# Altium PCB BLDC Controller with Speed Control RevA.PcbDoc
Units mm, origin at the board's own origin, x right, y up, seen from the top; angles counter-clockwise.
Board outline 60 x 60 mm, 2 copper layers (Top Layer, Bottom Layer), stack 1.575 mm thick; 48 components, 34 nets, 169 pads, 129 vias.
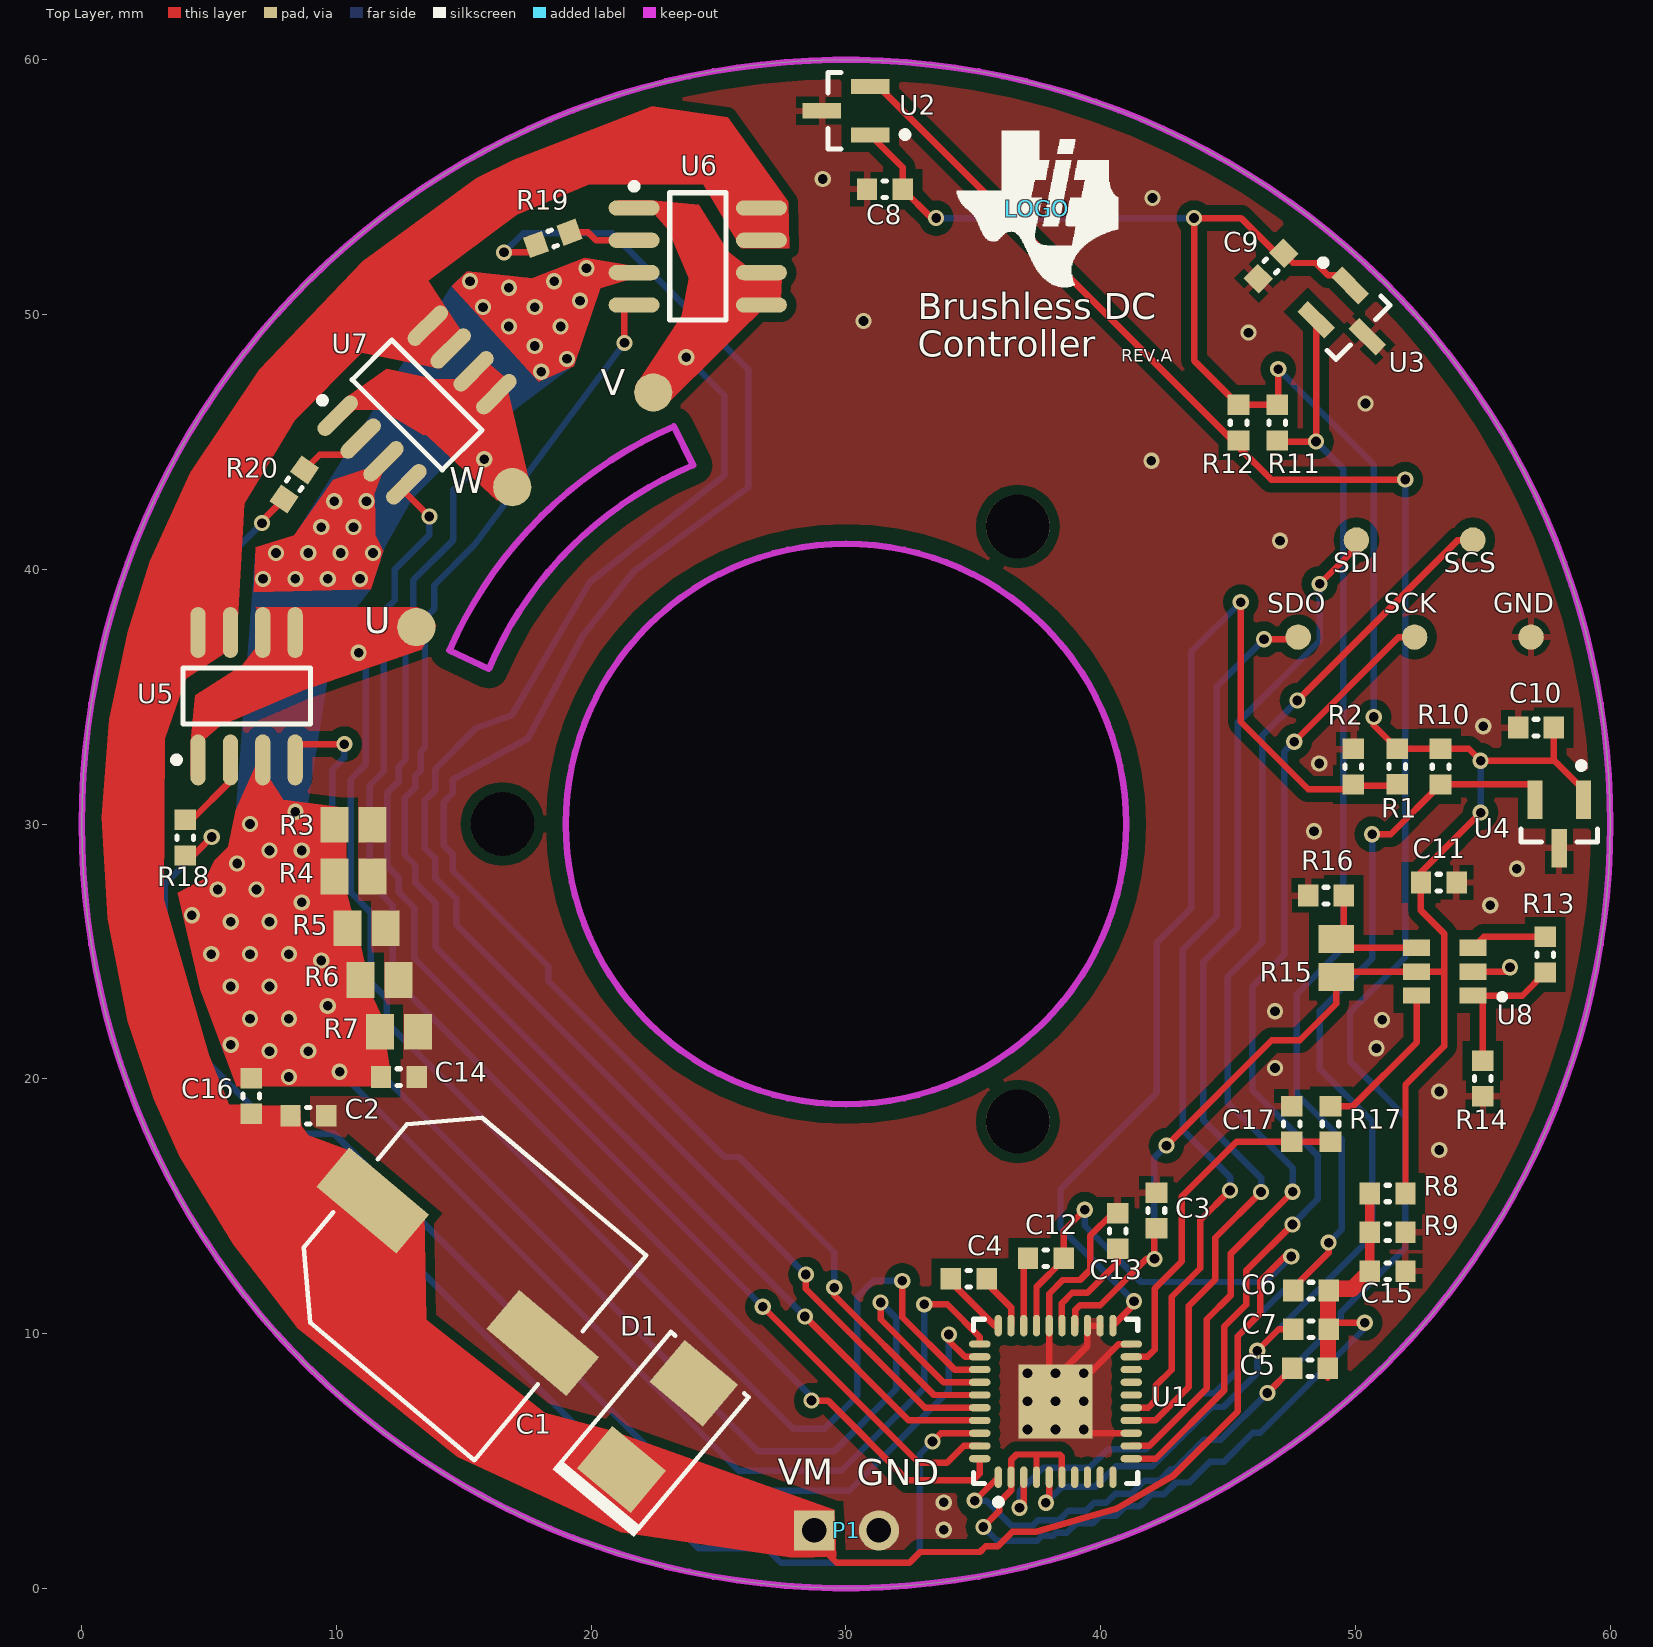
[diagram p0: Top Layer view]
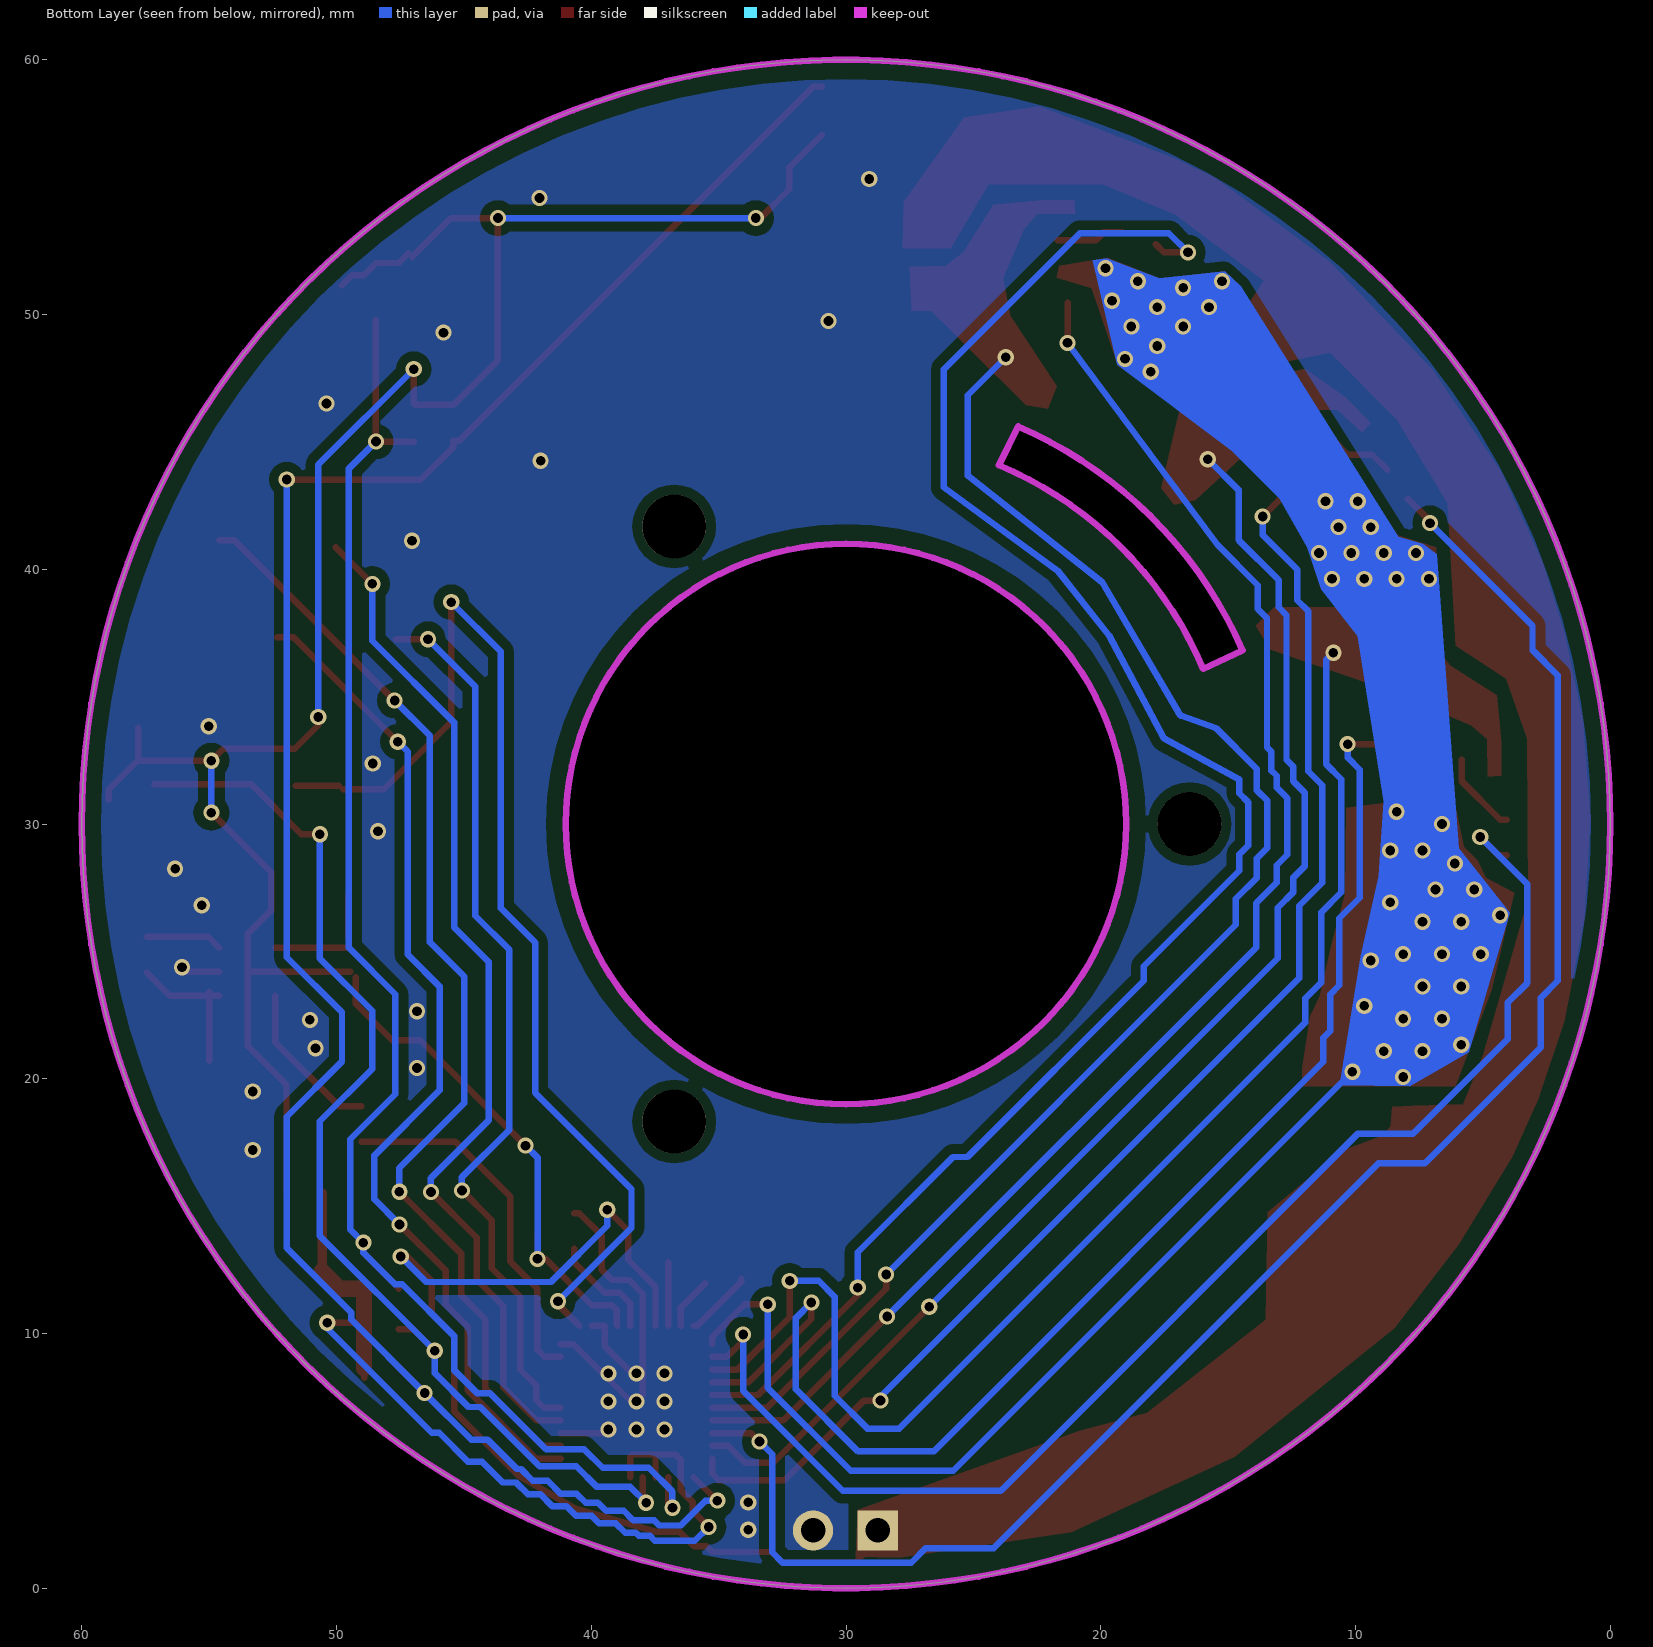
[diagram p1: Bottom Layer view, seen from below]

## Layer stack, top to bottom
Top Layer: signal copper 0.0356
Dielectric: core 1.5037, FR-4, Dk 4.8
Bottom Layer: signal copper 0.0356

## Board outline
30,0 cw(c30,30) 0,30 cw(c30,30) 30,60 cw(c30,30) 60,30 cw(c30,30)
cut-out: 30,19 cw(c30,30) 19,30 cw(c30,30) 30,41 cw(c30,30) 41,30 cw(c30,30)
cut-out: 15.976,36.086 14.431,36.816 cw(c30.032,29.993) 23.246,45.61 23.996,44.084 ccw(c29.827,30.217)

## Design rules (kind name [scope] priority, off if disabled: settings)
AcuteAngle [All] p1: minimum=1.50000000000000E+0001 checktracksonly=FALSE
AssemblyTestPointUsage [All] p1: valid=2
Clearance Clearance_BoardEdge_MountingHoles [OnCopper and InComponentClass('Mounting Holes') vs IsKeepOut] p1: gap=1.016
Clearance Clearance_BoardEdge_Poly [OnCopper and InPoly vs IsKeepOut] p2: gap=0.635
Clearance Clearance_BoardEdge [OnCopper and Not InComponentClass('Logo') and not InComponentClass('FiducialMark') and not InRegion(1000,500,4000,800) and Not IsKeepout and NOT IsRegion and NOT IsVia vs IsKeepOut] p3: gap=0.559
Clearance Clearance_Poly [InPolygon] p4: gap=0.381
Clearance [All] p5: gap=0.203
ComponentClearance ComponentClearance_Logo [InComponentClass('Logo')] p1: gap=1.27 collisioncheckmode=3 verticalgap=0.254 showdistances=FALSE
ComponentClearance ComponentClearance_ScrewToNut [(HasFootprint('NY PMS 440 0025 PH')) vs (HasFootprint('Keystone_1902C'))] p2: gap=0.127 collisioncheckmode=3 verticalgap=0.254 showdistances=FALSE
ComponentClearance ComponentClearance_MountingHoles [InComponentClass('Mounting Holes')] p3: gap=6.35 collisioncheckmode=3 verticalgap=2540 showdistances=FALSE
ComponentClearance ComponentClearance_SmallPassives [HasFootprint('0201*') or HasFootprint('0402*') or HasFootprint('0508') or HasFootprint('0603*') or HasFootprint('0612') or HasFootprint('0805*') or HasFootprint('0815*') or HasFootprint('0830*') or HasFootprint('1206*') or HasFootprint('1210*') or HasFootprint('1808*') or HasFootprint('1812*') or HasFootprint('1825*') or HasFootprint('2010*') or HasFootprint('2220*') or HasFootprint('2225*') or HasFootprint('2512*') or HasFootprint('2728*') or HasFootprint('3518*') vs HasFootprint('0201*') or HasFootprint('0402*') or HasFootprint('0508') or HasFootprint('0603*') or HasFootprint('0612') or HasFootprint('0805*') or HasFootprint('0815*') or HasFootprint('0830*') or HasFootprint('1206*') or HasFootprint('1210*') or HasFootprint('1808*') or HasFootprint('1812*') or HasFootprint('1825*') or HasFootprint('2010*') or HasFootprint('2220*') or HasFootprint('2225*') or HasFootprint('2512*') or HasFootprint('2728*') or HasFootprint('3518*')] p4: gap=0.508 collisioncheckmode=3 verticalgap=0.254 showdistances=FALSE
ComponentClearance ComponentClearance_THtoSMT [IsThruComponent vs IsSMTComponent] p5: gap=1.38 collisioncheckmode=3 verticalgap=0.762 showdistances=FALSE
ComponentClearance ComponentClearance_THtoTH [IsThruComponent vs IsThruComponent] p6: gap=0 collisioncheckmode=3 verticalgap=0.762 showdistances=FALSE
ComponentClearance [All] p7: gap=1.016 collisioncheckmode=3 verticalgap=0.254 showdistances=FALSE
DiffPairsRouting [All] p1: maxlimit=2.54 minlimit=0.254 mostfreqgap=0.254 maxuncoupledlength=25.4
FabricationTestPointUsage TestPointUsage [All] p1: valid=2 allowmultiple=FALSE
FabricationTestpoint Testpoint [All] p1: side=3 testpointundercomponent=TRUE minsize=1.016 maxsize=2.54 preferedsize=1.524 minholesize=0 maxholesize=1.016 preferedholesize=0.813 testpointgrid=0.025 allowsidetop=TRUE allowsidebottom=TRUE usegrid=TRUE gridtolerance=0
FanoutControl Fanout_LCC [IsLCC] p1: bgadir=Out bgaviamode=Centered fanoutstyle=Auto fanoutdirection=Alternating viagrid=0.025 // Fanout_LCC (Default Rule)
FanoutControl Fanout_BGA [IsBGA] p2: bgadir=Out bgaviamode=Centered fanoutstyle=Auto fanoutdirection=Alternating viagrid=0.025 // Fanout_BGA (Default Rule)
FanoutControl Fanout_Default [All] p4: bgadir=Out bgaviamode=Centered fanoutstyle=Auto fanoutdirection=Alternating viagrid=0.025 // Fanout_Default (Default Rule)
FanoutControl Fanout_Small [(CompPinCount < 5)] p5: bgadir=Out bgaviamode=Centered fanoutstyle=Auto fanoutdirection=OutThenIn viagrid=0.025 // Fanout_Small (Default Rule)
HoleSize [All] p1: absolutevalues=TRUE maxlimit=6.375 minlimit=0.203 maxpercent=80.000 minpercent=20.000
MinimumAnnularRing [All] p1: minimumring=0.127
MinimumSolderMaskSliver MinimumSolderMaskSliver_Logo [InComponentClass('Logo') vs InComponentClass('Logo')] p1: minsoldermaskwidth=0.018
MinimumSolderMaskSliver [All] p2: minsoldermaskwidth=0.076
PlaneConnect [All] p1: planeconnectstyle=Relief reliefexpansion=0.254 reliefentries=4 reliefconductorwidth=0.254 reliefairgap=0.254
PolygonConnect PolygonConnect_1 [IsNamedPolygon('Top GND plane') or IsNamedPolygon('Bottom GND plane') vs not ( InComponent('U1') or InComponent('C1') or InComponent('C2') or InComponent('D1') or InComponent('P1') or InComponent('P2') or InComponent('R3') or InComponent('R4') or InComponent('R5') or InComponent('R6') or InComponent('R7') or InComponent('C14') or IsStitchingVia or IsVia)] p1: connectstyle=Relief reliefconductorwidth=0.254 reliefentries=4 polygonreliefangle="90 Angle" airgapwidth=0.254
PolygonConnect [All] p2: connectstyle=Direct reliefconductorwidth=0.254 reliefentries=4 polygonreliefangle="90 Angle" airgapwidth=0.254
RoutingVias [All] p1: holewidth=0.406 width=0.864 viastyle="Through Hole" minholewidth=0.203 minwidth=0.635 maxholewidth=1.016 maxwidth=1.651
SMDToCorner [All] p1: distance=0
SilkToSilkClearance [All] p1: silktosilkclearance=0.076
SilkscreenOverComponentPads [All] p1: minsilkscreentomaskgap=0.051
SolderMaskExpansion [All] p1: expansion=0.076
Width [All] p1: maxlimit=2.54 minlimit=0.152 preferedwidth=0.254 checkconnectedcopper=TRUE
14 further rules are at their usual default settings.

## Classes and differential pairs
component class Logo: LOGO

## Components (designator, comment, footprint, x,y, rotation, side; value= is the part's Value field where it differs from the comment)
C1 "PartNumber" SM_RADIAL_G 14.757,12.417 r320 top
C2 "PartNumber" 0603L 8.89,18.542 r0 top
C3 "PartNumber" 0603L 42.189,14.826 r90 top
C4 "PartNumber" 0603L 34.819,12.153 r0 top
C5 "PartNumber" 0603L 48.218,8.636 r0 top
C6 "PartNumber" 0603L 48.26,11.684 r0 top
C7 "PartNumber" 0603L 48.26,10.16 r0 top
C8 "PartNumber" 0603L 31.523,54.925 r180 top
C9 "PartNumber" 0603L 46.686,51.91 r225 top
C10 "PartNumber" 0603L 57.087,33.787 r180 top
C11 "PartNumber" 0603L 53.274,27.702 r0 top
C12 "PartNumber" 0603L 37.846,12.954 r0 top
C13 "PartNumber" 0603L 40.667,14.02 r90 top
C14 "PartNumber" 0603L 12.446,20.066 r0 top
C15 "PartNumber" 0603L 51.266,12.446 r0 top
C16 "PartNumber" 0603L 6.647,19.32 r90 top
C17 "PartNumber" 0603L 47.498,18.226 r90 top
D1 "PartNumber" SMB 22.606,6.35 r50 top
LOGO "Texas Instruments" TI_Symbol_Overlay_Medium 37.517,54.159 r0 top
P1 "JUMPER_2X100MIL" "2PIN HEADER" 27.601,1.045 r0 top
R1 "PartNumber" 0603L 51.642,32.254 r90 top
R2 "PartNumber" 0603L 49.917,32.253 r270 top
R3 "PartNumber" 0805L 10.668,29.972 r180 top
R4 "PartNumber" 0805L 10.668,27.94 r180 top
R5 "PartNumber" 0805L 11.176,25.908 r180 top
R6 "PartNumber" 0805L 11.684,23.876 r180 top
R7 "PartNumber" 0805L 12.446,21.844 r180 top
R8 "PartNumber" 0603L 51.266,15.494 r0 top
R9 "PartNumber" 0603L 51.266,13.97 r180 top
R10 "PartNumber" 0603L 53.342,32.253 r90 top
R11 "PartNumber" 0603L 46.936,45.754 r90 top
R12 "PartNumber" 0603L 45.412,45.754 r90 top
R13 "PartNumber" 0603L 57.457,24.87 r90 top
R14 "PartNumber" 0603L 55.003,20.007 r90 top
R15 "PartNumber" 0805L 49.247,24.742 r270 top
R16 "PartNumber" 0603L 48.847,27.192 r0 top
R17 "PartNumber" 0603L 49.022,18.226 r90 top
R18 "PartNumber" 0603L 4.064,29.464 r90 top
R19 "PartNumber" 0603L 18.488,52.991 r20 top
R20 "PartNumber" 0603L 8.341,43.333 r55 top
U1 "DRV8308" RHA0040A 38.229,7.332 r90 top
U2 "DRV5013" DBZ0003A_N 30,58 r180 top
U3 "DRV5013" DBZ0003A_N 49.799,49.799 r315 top
U4 "DRV5013" DBZ0003A_N 58,30 r270 top
U5 "CSD88537ND" SO-8_N 6.469,35.018 r90 top
U6 "CSD88537ND" SO-8_N 24.181,52.281 r0 top
U7 "CSD88537ND" SO-8_N 13.16,46.452 r45 top
U8 "LTC6992IS6-2" SOT23-6 53.47,24.202 r180 top

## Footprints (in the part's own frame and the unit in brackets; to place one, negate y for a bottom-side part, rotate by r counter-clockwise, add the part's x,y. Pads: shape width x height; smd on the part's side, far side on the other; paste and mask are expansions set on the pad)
"2PIN HEADER" [mil]
  rect 62x62 hole 38: 1(45.32,48.03)
  round 62 hole 38: 2(145.32,48.03)
0603L [mm] "0603 from SM-752 data"
  rect 0.8x0.85 smd: 1(-0.7,0) 2(0.7,0)
  silkscreen extent -0.07,-0.33 0.07,0.33, body extent -0.87,-0.47 0.87,0.47, height 0.85
0805L [mm] "0805 from SM-752 data"
  rect 1.1x1.4 smd: 1(-0.75,0) 2(0.75,0)
  body extent -1.1,-0.72 1.1,0.72, height 1.1
DBZ0003A_N [mm] "SOT23, 3-Leads, Body 2.9x1.3mm, Pitch 0.95mm, Lead Span 2.4mm, IPC Medium Density"
  rect 1.5x0.6 smd: 1(-0.95,0.95) 2(-0.95,-0.95) 3(0.95,0)
  silkscreen extent -2.44,-1.5 0.7,1.5, body extent -0.7,-1.52 0.7,1.52, height 1.12
RHA0040A [mm] "QFN, 40-Leads, Body 6x6mm, Pitch 0.5mm, Thermal Pad 2.9x2.9mm, TI Recommended"
  oval 0.85x0.28 smd paste-0.025 mask+0.07: 1(-2.975,2.25) 2(-2.975,1.75) 3(-2.975,1.25) 4(-2.975,0.75) 5(-2.975,0.25) 6(-2.975,-0.25) 7(-2.975,-0.75) 8(-2.975,-1.25) 9(-2.975,-1.75) 10(-2.975,-2.25) 21(2.975,-2.25) 22(2.975,-1.75) 23(2.975,-1.25) 24(2.975,-0.75) 25(2.975,-0.25) 26(2.975,0.25) 27(2.975,0.75) 28(2.975,1.25) 29(2.975,1.75) 30(2.975,2.25)
  oval 0.28x0.85 smd paste-0.025 mask+0.07: 11(-2.25,-2.975) 12(-1.75,-2.975) 13(-1.25,-2.975) 14(-0.75,-2.975) 15(-0.25,-2.975) 16(0.25,-2.975) 17(0.75,-2.975) 18(1.25,-2.975) 19(1.75,-2.975) 20(2.25,-2.975) 31(2.25,2.975) 32(1.75,2.975) 33(1.25,2.975) 34(0.75,2.975) 35(0.25,2.975) 36(-0.25,2.975) 37(-0.75,2.975) 38(-1.25,2.975) 39(-1.75,2.975) 40(-2.25,2.975)
  rect 2.9x2.9 smd paste-2.45 mask+0.07: 41(0,0)
  silkscreen extent -4.08,-3.22 3.22,3.22, body extent -3.08,-3.08 3.08,3.08, height 1
SM_RADIAL_G [mm] "10 x 10.2mm:  Panasonic G"
  rect 4.1x2 smd: 1(-4.35,0) 2(4.35,0)
  silkscreen extent -5.25,-5.25 5.25,5.25, body extent -5.26,-5.26 5.26,5.26, height 10.5
SMB [mm] "Molded Diode, 2-Leads, Body 5.4x3.6mm, IPC Medium Density, based on OnSemi component dimensions"
  rect 2.159x2.743 smd: 1(-2.21,0) 2(2.21,0)
  silkscreen extent -3.94,-2.08 3.18,2.08, body extent -2.7,-1.8 2.7,1.8, height 2.32
SO-8_N [mm] "SOIC, 8-Leads, Body 4.9x3.9mm, Pitch 1.27mm, IPC Medium Density"
  oval 2x0.6 smd: 1(-2.5,1.905) 2(-2.5,0.635) 3(-2.5,-0.635) 4(-2.5,-1.905) 5(2.5,-1.905) 6(2.5,-0.635) 7(2.5,0.635) 8(2.5,1.905)
  silkscreen extent -2.62,-2.5 1.1,2.88, body extent -2,-2.5 2,2.5, height 1.75
SOT23-6 [mil]
  rect 42x25 smd: 1(-45,37) 2(-45,0) 3(-45,-37) 4(42,-37) 5(42,0) 6(42,37)
TI_Symbol_Overlay_Medium [mm]
  silkscreen extent -3.16,-3.09 3.16,3.06

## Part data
C1: library part EEE-FC1H101P
C2 C3 C4 C5 C6 C7 C8 C9 C10 C11 C12 C13 C14 C15 C16 C17: library part 0603YC104JAT2A
D1: library part 10BQ030TRPBF
LOGO: library part TI_Logo, "Texas Instrument Corporate Signature"
P1: "Header, Male 2-pin, 100mil spacing,"
R1 R2 R8 R9 R10 R11 R12 R13 R14 R16 R17 R18 R19 R20: library part CRCW06031K00FKEA
R3 R4 R5 R6 R7: library part CRCW08051K13FKEA
R15: library part CRCW08051K00FKEA
U2 U3 U4: library part DRV5xxxDBZ, "Hall sensor"
U5 U6 U7: library part FDS8949, "MOSFET N-CH DUAL 30V 3.5A SOP8"
U8: library part LTC6992-2

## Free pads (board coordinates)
  round 1.5 smd: 0(13.131,37.73) 0(16.895,43.225) 0(22.431,46.944)
  round 2.5 hole 2.5 unplated: 0(16.513,30) 0(36.744,18.32) 0(36.744,41.68)
  round 1 smd: 0(47.752,37.338) 0(50.038,41.148) 0(52.324,37.338) 0(54.61,41.148) 0(56.896,37.338)

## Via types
v1: diameter 0.635, hole 0.381, Top Layer to Bottom Layer, tented both sides, 120 vias
v2: diameter 0.635, hole 0.381, Top Layer to Bottom Layer, 9 vias

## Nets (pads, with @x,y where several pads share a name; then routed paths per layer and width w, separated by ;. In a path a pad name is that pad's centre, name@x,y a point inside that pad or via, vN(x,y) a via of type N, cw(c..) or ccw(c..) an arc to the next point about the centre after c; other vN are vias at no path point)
2.5V: C5.2 C6.2 C7.2 C15.1 R8.1 R9.2 U1.2 U1.4 U1.6 | length 35.6
  Top Layer w0.254: v1(35.392,2.404) 36.026,3.037 36.026,3.382 36.479,3.835 U1.2 36.479,5.032 36.693,5.246 37.414,5.246 ; U1.4 37.479,5.182 ; 37.479,5.246 38.393,5.246 38.479,5.161 U1.6 ; C7.2@48.917,10.418 v1(50.367,10.418) ; C5.2@48.918,8.261 C5.2
  Top Layer w0.381: C15.1 R8.1
  Top Layer w0.635: C6.2@48.909,11.755 49.875,11.755 C15.1 ; C5.2 C6.2@48.918,11.746
  Bottom Layer w0.254: v1(35.392,2.404) 35.938,1.857 37.504,1.857 37.71,2.063 38.133,2.063 38.246,2.175 38.671,2.175 39.034,2.539 39.689,2.539 39.985,2.835 40.589,2.835 40.979,3.224 41.539,3.224 42.007,3.692 42.499,3.692 42.954,4.147 43.473,4.147 44.289,4.963 44.841,4.963 45.974,6.096 46.262,6.096 50.367,10.201 v1(50.367,10.418)
CLK: R17.2 U8.6 | length 6.3
  Top Layer w0.254: R17.2 49.905,18.926 52.403,21.424 U8.6
CLKIN: C17.1 R17.1 U1.19 | length 14.2
  Top Layer w0.254: U1.19 41.838,9.082 42.115,9.359 42.115,11.759 43.182,12.826 43.182,15.375 45.332,17.526 C17.1 R17.1
CP1: C4.1 U1.30 | length 2.7
  Top Layer w0.254: C4.1 34.119,12.019 35.831,10.307 U1.30
CP2: C4.2 U1.29 | length 2.1
  Top Layer w0.254: C4.2@35.519,11.979 36.479,11.019 U1.29
DIR: R1.1 R2.2 U1.21 | length 44.6
  Top Layer w0.254: U1.21 41.305,11.133 v1(41.305,11.261) ; v1(45.496,38.711) 45.496,34.014 48.143,31.367 R2.2@49.732,31.367 ; R2.2@49.917,31.509 R1.1@51.596,31.509
  Bottom Layer w0.254: v1(41.305,11.261) 38.421,14.144 38.421,15.662 42.201,19.442 42.201,25.344 43.548,26.692 43.548,36.764 v1(45.496,38.711)
DIV: R15.1 R16.2 U8.4 | length 4.5
  Top Layer w0.254: R15.1@49.538,25.142 U8.4 ; R15.1@49.547,25.572 R16.2
GND: C1.2 C2.2 C3.2 C8.2 C9.2 C10.2 C11.2 C13.2 C14.2 C15.2 C17.2 D1.2 P1.2 pad.0@56.896,37.338 R2.1 R3.1 R4.1 R5.1 R6.1 R7.1 R9.1 R14.1 R16.1 U1.13 U1.20 U1.22 U1.23 U1.26 U1.41 U2.3 U3.3 U4.3 U8.2 | length 18.6
  Top Layer w0.254: U1.41@37.979,7.582 U1.26 37.979,11.563 38.513,12.097 39.188,12.097 39.582,12.491 39.582,13.833 40.469,14.72 C13.2 ; U1.41@38.316,8.344 39.479,9.507 U1.23 U1.22 ; U1.41@38.453,7.332 40.703,9.582 U1.20 ; U1.41@39.479,6.082 U1.13 ; U8.2 55.897,24.202 v1(56.071,24.376)
  other v1: 33.835,2.295 33.835,3.367 53.293,17.198 53.293,19.494 46.84,20.42 50.825,21.194 51.049,22.31 46.84,22.649 55.294,26.812 56.339,28.246 48.376,29.716 48.577,32.372 55.015,33.837 47.037,41.123 41.988,44.26 50.399,46.505 45.804,49.291 30.687,49.747 42.035,54.579 29.087,55.325
  other v2: 37.129,6.232 38.229,6.232 39.329,6.232 37.129,7.332 38.229,7.332 39.329,7.332 37.129,8.432 38.229,8.432 39.329,8.432
HU+: C5.1 R12.1 U1.1 U2.2 | length 84.2
  Top Layer w0.254: U2.2 31.277,58.95 45.173,45.054 R12.1 45.412,44.801 46.692,43.522 v1(51.955,43.522) ; v1(35.049,3.435) 35.056,3.435 U1.1 ; v1@35.051,3.429 v1@35.053,3.431 ; v1(46.544,7.662) C5.1
  Bottom Layer w0.254: v1(35.049,3.435) 35.518,3.435 36.492,2.46 37.335,2.46 37.537,2.662 38.36,2.662 38.731,3.033 39.421,3.033 39.74,3.352 40.218,3.352 40.566,3.699 41.196,3.699 41.713,4.216 42.301,4.216 42.762,4.677 42.921,4.677 44.076,5.832 44.714,5.832 v1(46.544,7.662) 49.416,10.534 49.416,10.816 51.955,13.356 51.955,18.508 49.787,20.675 49.787,22.604 51.955,24.772 v1(51.955,43.522)
HV+: C6.1 R11.1 U1.3 U3.2 | length 61.3
  Top Layer w0.254: v1(36.813,3.154) 36.979,3.319 U1.3 ; R11.1@46.975,45.015 v1(48.456,45.015) U3.2 ; C6.1@47.56,11.753 47.56,11.785 48.949,13.174 v1(48.949,13.565)
  Bottom Layer w0.254: v1(36.813,3.154) 36.813,3.791 37.746,4.724 39.552,4.724 40.283,5.455 41.777,5.455 43.982,7.66 44.488,7.66 45.372,8.545 45.372,9.884 47.424,11.936 47.709,11.936 48.949,13.176 v1(48.949,13.565) 49.464,14.08 49.464,17.621 47.691,19.394 47.691,23.316 49.516,25.141 49.516,43.955 v1(48.456,45.015)
HW+: C7.1 R10.1 U1.5 U4.2 | length 45.3
  Top Layer w0.254: v1(37.846,3.35) 37.979,3.483 U1.5 ; v1(46.149,9.321) 46.987,10.16 C7.1 ; v1(50.655,29.599) 51.388,29.599 R10.1 U4.2@57.157,31.553
  Bottom Layer w0.254: v1(37.846,3.35) 38.47,3.974 39.778,3.974 40.588,4.784 42.03,4.784 44.358,7.112 44.818,7.112 46.149,8.443 v1(46.149,9.321) 50.655,13.828 50.655,18.325 48.598,20.382 48.598,22.665 50.655,24.722 v1(50.655,29.599)
ISENSE: C14.1 C16.2 R3.2 R4.2 R5.2 R6.2 R7.2 U1.31 U5.3 U6.3 U7.3 | length 37.1
  Top Layer w0.254: v1(33.072,11.142) 33.971,11.142 35.254,9.859 U1.31
  Bottom Layer w0.254: v1(10.121,20.272) 25.787,4.605 29.818,4.605 33.072,7.86 v1(33.072,11.142)
  other v1: 8.128,20.066 7.366,21.082 8.89,21.082 5.842,21.336 6.604,22.352 8.128,22.352 9.652,22.86 5.842,23.622 7.366,23.622 9.398,24.638 5.08,24.892 6.604,24.892 8.128,24.892 5.842,26.162 7.366,26.162 4.318,26.416 8.636,26.924 5.334,27.432 6.858,27.432 6.096,28.448 7.366,28.956 8.636,28.956 6.604,30 8.382,30.48 7.112,39.624 8.382,39.624 9.652,39.624 10.922,39.624 7.62,40.64 8.89,40.64 10.16,40.64 11.43,40.64 9.398,41.656 10.668,41.656 9.906,42.672 11.176,42.672 18.034,47.752 19.05,48.26 17.78,48.768 16.764,49.53 18.796,49.53 15.748,50.292 17.78,50.292 19.558,50.546 16.764,51.054 15.24,51.308 18.542,51.308 19.812,51.816
MOD: R13.1 R14.2 U8.1 | length 5.9
  Top Layer w0.254: U8.1 56.549,23.262 R13.1 ; R14.2 U8.1@55.003,23.407
SCLK: pad.0@52.324,37.338 U1.11 | length 39.9
  Top Layer w0.254: U1.11 42.162,5.082 44.842,7.762 44.842,10.258 45.708,11.125 45.708,12.459 v1(47.528,14.279) ; v1(47.596,33.228) 51.706,37.338 pad.0@52.324,37.338
  Bottom Layer w0.254: v1(47.528,14.279) 48.513,15.264 48.513,16.987 45.956,19.544 45.956,23.624 47.21,24.878 47.21,32.842 v1(47.596,33.228)
SCS: pad.0@54.61,41.148 U1.12 | length 44
  Top Layer w0.254: U1.12 41.904,5.582 44.162,7.84 44.162,10.555 45.114,11.507 45.114,13.142 v1(47.535,15.563) ; v1(47.722,34.846) 54.024,41.148 pad.0@54.61,41.148
  Bottom Layer w0.254: v1(47.535,15.563) 47.535,16.491 44.984,19.042 44.984,24.009 46.336,25.362 46.336,33.461 v1(47.722,34.846)
SDATAI: pad.0@50.038,41.148 U1.14 | length 40.4
  Top Layer w0.254: U1.14 42.142,6.582 43.463,7.903 43.463,11.083 44.5,12.12 44.5,13.756 v1(46.296,15.552) ; v1(48.595,39.427) pad.0@50.038,40.87
  Bottom Layer w0.254: v1(46.296,15.552) 46.296,16.098 44.033,18.361 44.033,24.587 45.387,25.941 45.387,33.986 48.595,37.194 v1(48.595,39.427)
SDATAO: pad.0@47.752,37.338 U1.15 | length 35.5
  Top Layer w0.254: U1.15 41.864,7.082 42.154,7.372 42.154,7.944 42.788,8.578 42.788,11.439 43.904,12.555 43.904,14.44 v1(45.077,15.613) ; v1(46.407,37.255) pad.0@47.669,37.255
  Bottom Layer w0.254: v1(45.077,15.613) 45.077,16.138 43.215,18 43.215,25.063 44.551,26.399 44.551,35.399 v1(46.407,37.255)
SET: R13.2 U8.3 | length 3
  Top Layer w0.254: U8.3 55.041,25.57 R13.2
U: pad.0@13.131,37.73 U1.33 U5.1 U5.5 U5.6 | length 52.3
  Top Layer w0.254: v1(32.211,12.063) 32.211,10.632 34.261,8.582 U1.33
  Bottom Layer w0.254: v1(10.866,36.725) 11.151,36.44 11.151,32.356 10.553,31.757 10.553,27.322 11.334,26.541 11.334,23.792 11.972,23.153 11.972,22.205 27.91,6.267 29.158,6.267 30.443,7.552 30.443,11.433 31.073,12.063 v1(32.211,12.063)
UHS: R18.1 U1.32 | length 53.3
  Top Layer w0.254: R18.1 4.371,28.764 v1(5.1,29.492) ; v1(34.039,9.956) 34.039,9.718 34.675,9.082 U1.32
  Bottom Layer w0.254: v1(5.1,29.492) 3.246,27.639 3.246,23.758 4.027,22.978 4.027,21.554 7.75,17.83 9.915,17.83 23.918,3.827 30.126,3.827 34.039,7.74 v1(34.039,9.956)
UHS_GATE: R18.2 U5.2 | length 3.2
  Top Layer w0.254: R18.2 4.311,30.164 5.834,31.686 U5.2
ULS_GATE: U1.34 U5.4 | length 52.6
  Top Layer w0.254: U5.4@8.266,33.136 v1(10.305,33.136) ; v1(31.359,11.214) 31.359,10.554 33.831,8.082 U1.34
  Bottom Layer w0.254: v1(10.305,33.136) 10.305,32.609 9.828,32.132 9.828,27.1 10.63,26.299 10.63,23.672 10.981,23.321 10.981,21.884 11.262,21.603 11.262,20.663 26.556,5.368 29.527,5.368 31.965,7.806 31.965,10.608 v1(31.359,11.214)
V: pad.0@22.431,46.944 U1.36 U6.1 U6.5 U6.6 | length 57.4
  Top Layer w0.254: v1(28.425,12.315) 28.425,11.755 33.098,7.082 U1.36
  Bottom Layer w0.254: v1(23.731,48.323) 25.224,46.83 25.224,43.68 19.94,39.489 16.867,34.256 15.478,33.767 13.865,32.154 13.865,31.318 13.456,30.909 13.456,29.063 13.865,28.654 13.865,27.894 14.694,27.065 14.694,26.047 v1(28.425,12.315)
VCP: C12.1 U1.28 | length 2.5
  Top Layer w0.254: U1.28 C12.1@36.979,12.787
VHS: R19.1 U1.35 | length 69.3
  Top Layer w0.254: v1(16.576,52.443) 17.521,52.443 R19.1 ; v1(29.541,11.797) 29.541,11.497 33.457,7.582 U1.35
  Bottom Layer w0.254: v1(16.576,52.443) 17.327,53.193 20.817,53.193 26.156,47.855 26.156,43.212 21.688,39.939 19.675,37.404 17.511,33.357 14.562,31.749 14.562,31.208 14.215,30.861 14.215,29.151 14.562,28.804 14.562,28.161 18.307,24.416 18.307,23.85 25.23,16.927 25.796,16.927 29.541,13.182 v1(29.541,11.797)
VHS_GATE: R19.2 U6.2 | length 2.7
  Top Layer w0.254: R19.2 19.873,53.231 20.187,52.916 U6.2
VINT: C13.1 U1.25 | length 4.3
  Top Layer w0.254: U1.25 38.479,11.186 38.887,11.594 39.48,11.594 40.667,12.781 C13.1
VLS_GATE: U1.37 U6.4 | length 57.9
  Top Layer w0.254: v1(21.301,48.89) U6.4@21.301,50.461 ; v1(28.386,10.664) 32.468,6.582 U1.37
  Bottom Layer w0.254: v1(21.301,48.89) 15.394,40.94 13.832,39.379 13.832,38.443 13.471,38.082 13.471,33.016 13.297,32.842 13.297,32.094 13.093,31.891 13.093,31.43 12.68,31.017 12.68,28.796 13.093,28.383 13.093,27.701 13.897,26.897 13.897,25.153 v1(28.386,10.664)
VM: C1.1 C2.1 C12.2 C16.1 D1.1 P1.1 U1.27 U5.7 U5.8 U6.7 U6.8 U7.7 U7.8 | length 41.8
  Top Layer w0.254: P1.1@28.749,2.266 28.749,1.885 29.639,0.995 32.491,0.995 32.914,1.419 35.257,1.419 35.484,1.646 35.964,1.646 36.534,2.216 37.464,2.216 40.604,3.121 42.836,4.399 45.375,6.939 45.375,9.892 46.254,10.771 46.254,12.048 47.23,13.023 v1(47.481,13.023) ; U1.27 37.479,11.825 C12.2@38.546,12.892 ; C12.2 38.546,14.026 v1(39.376,14.856)
  Bottom Layer w0.254: v1(39.376,14.856) 39.376,14.222 41.579,12.019 46.477,12.019 v1(47.481,13.023)
VREG: C3.1 C8.1 C9.1 C10.1 C11.1 R1.2 R8.2 R10.2 R11.2 R12.2 R15.2 U1.24 U2.1 U3.1 U4.1 U8.5 | length 102.4
  Top Layer w0.254: U2.1 32.223,55.777 C8.1 33.359,53.789 v1(33.539,53.789) ; U1.24 39.008,10.337 39.008,10.932 39.188,11.111 39.982,11.111 41.799,12.928 v1(42.111,12.928) C3.1@42.111,14.047 ; v1(42.58,17.373) 46.718,21.51 47.812,21.51 49.247,22.945 R15.2 ; R11.2 R12.2 43.665,48.201 v1(43.665,53.789) 45.507,53.789 C9.1@47.036,52.259 ; R11.2@46.971,46.489 v1(46.971,47.857) ; C9.1 47.561,52.025 48.447,52.025 48.924,51.548 49.394,51.548 U3.1 ; R15.2@49.464,24.202 U8.5 53.465,24.202 ; v1(50.717,34.201) 50.717,33.879 R1.2 54.444,32.954 v1(54.917,32.482) 57.758,32.482 ; R8.2 51.966,19.761 53.48,21.275 53.48,25.698 52.574,26.605 C11.1 52.574,28.105 v1(54.917,30.447) ; C10.1 57.787,32.511 58.95,31.349 U4.1
  Bottom Layer w0.254: v1(33.539,53.789) v1(43.665,53.789) ; v1(42.111,12.928) 42.111,16.903 v1(42.58,17.373) ; v1(46.971,47.857) 50.717,44.111 v1(50.717,34.201) ; v1(54.917,30.447) v1(54.917,32.482)
W: pad.0@16.895,43.225 U1.39 U7.1 U7.5 U7.6 | length 52.3
  Top Layer w0.254: v1(26.734,11.047) 32.856,4.925 33.963,4.925 34.62,5.582 U1.39
  Bottom Layer w0.254: v1(15.797,44.321) 14.59,43.114 14.59,41.153 13.015,39.578 13.015,38.506 12.706,38.198 12.706,32.527 12.432,32.252 12.432,31.669 11.997,31.234 11.997,28.335 12.432,27.9 12.432,27.328 13.05,26.709 13.05,24.73 v1(26.734,11.047)
WHS: R20.1 U1.38 | length 69.5
  Top Layer w0.254: v1(7.073,41.811) 7.073,41.892 R20.1 ; v1(33.398,5.753) 33.727,6.082 U1.38
  Bottom Layer w0.254: v1(7.073,41.811) 3.048,37.787 3.048,36.827 2.054,35.833 2.054,23.843 2.717,23.18 2.717,21.234 7.273,16.678 9.095,16.678 24.2,1.574 26.864,1.574 27.441,0.997 32.491,0.997 32.901,1.407 32.901,5.256 v1(33.398,5.753)
WHS_GATE: R20.2 U7.2 | length 2.7
  Top Layer w0.254: R20.2 9.335,44.498 10.308,44.498 U7.2
WLS_GATE: U1.40 U7.4 | length 53.1
  Top Layer w0.254: U7.4@12.485,43.228 v1(13.642,42.07) ; v1(28.644,7.363) 29.292,7.363 32.415,4.24 34.995,4.24 35.254,4.498 U1.40
  Bottom Layer w0.254: v1(13.642,42.07) 13.642,41.346 12.286,39.99 12.286,38.789 11.856,38.358 11.856,32.071 11.306,31.521 11.306,27.689 12.207,26.788 12.207,23.953 28.644,7.516 v1(28.644,7.363)
pads on no net: U1.7 U1.8 U1.9 U1.10 U1.16 U1.17 U1.18

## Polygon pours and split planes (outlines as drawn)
GND on Bottom Layer "Bottom GND plane" (solid, remove dead copper, pour order 8): 30,0 cw(c30,30) 0,30 cw(c30,30) 30,60 cw(c30,30) 60,30 cw(c30,30)
GND on Top Layer "Top GND plane" (solid, remove dead copper, pour order 6): 30,0 cw(c30,30) 0,30 cw(c30,30) 30,60 cw(c30,30) 60,30 cw(c30,30)

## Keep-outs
Keep-Out Layer:
  circle w0.254: c30,30 r11
  circle w0.254: c30,30 r30
  lines w0.254: 14.431,36.815 cw(c30.032,29.993) 23.246,45.61 23.996,44.084 ccw(c29.827,30.217) 15.976,36.086 14.431,36.816
  text ".Layer_Name" at 14.656,-21.806 h1.52

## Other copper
Top Layer:
  region net ISENSE: 21.634,51.915 19.739,52.237 17.68,51.432 15.139,51.692 14.516,51.113 17.938,47.364 19.313,47.971 20.354,51.035 21.718,51.438
  region net ISENSE: 11.175,43.944 9.875,43.523 8.329,41.331 6.82,40.856 6.746,39.106 11.342,39.21 11.829,40.727 11.514,41.34 11.522,42.225 11.485,42.956 11.872,43.99
  region net V: 23.843,51.475 23.56,49.958 21.734,47.18 22.081,46.293 22.93,46.435 27.353,50.845
  region net W: 13.402,45.376 16.293,42.719 17.111,42.538 17.632,43.176 16.644,47.363
  region net U: 8.305,35.117 13.317,36.848 13.909,37.786 13.195,38.512 6.83,38.523
  region net W: 9.393,45.762 10.357,46.735 11.97,47.867 13.889,47.464 14.701,47.461 15.624,48.384 16.98,47.231 15.901,46.142 13.419,45.267 11.738,46.254 10.715,46.259 9.737,45.368
  region net V: 21.044,54.487 22.382,54.487 24.209,54.321 25.383,52.47 26.092,51.921 27.495,51.884 27.421,50.15 24.376,50.15 23.013,53.329 22.492,53.947 21.004,53.96
  region net U: 4.283,31.886 4.283,33.224 4.449,35.051 6.3,36.224 6.849,36.933 6.885,38.336 8.62,38.262 8.62,35.217 5.441,33.854 4.822,33.333 4.81,31.846
  region net ISENSE: 7.351,32.172 7.351,31.794 7.913,30.948 10.364,30.632 10.391,27.281 10.932,25.295 11.391,23.242 11.769,22.458 12.08,20.418 12.08,19.702 6.085,19.69 4.655,23.503 3.763,27.298 4.881,27.896 5.193,28.561 5.742,29.112 6.034,30.548 6.838,32.343
  region net VM: 29.61,1.237 29.538,3.068 20.829,6.186 18.173,6.892 13.528,10.538 13.44,14.75 10.533,17.18 8.889,17.776 8.615,18.148 8.556,18.891 7.766,18.935 5.761,18.99 4.977,20.946 3.223,27.047 3.26,33.348 4.072,35.702 6.071,36.997 6.377,42.571 8.35,45.842 10.98,48.509 14.072,47.873 15.097,49.058 13.604,51.338 17.083,53.913 19.883,55.104 24.4,55.11 25.892,52.611 27.777,52.604 27.731,54.438 25.357,57.753 22.384,58.178 16.954,56.077 15.483,55.346 11.026,52.085 6.958,47.84 4.261,43.793 2.669,40.302 1.792,37.534 1.072,34.086 0.781,30.262 1.024,26.274 1.8,22.256 2.82,19.22 3.838,16.941 5.949,13.498 8.479,10.206 14.737,5.151 21.159,2.194 27.901,1.185
  text ".Layer_Name" at 14.656,-21.806 h1.52
Bottom Layer:
  region net ISENSE: 20.304,52.125 19.771,52.209 17.701,51.429 15.134,51.699 14.498,51.118 8.316,41.274 7.361,41.008 6.8,40.599 5.952,29.043 3.933,26.521 5.552,21.034 7.869,19.696 10.614,19.744 9.79,24.808 9.075,27.941 8.893,30.9 9.912,37.371 11.342,39.21 11.893,40.864 12.964,42.772 14.849,44.658 19.346,48.025
  text ".Layer_Name" at 14.656,-21.806 h1.52

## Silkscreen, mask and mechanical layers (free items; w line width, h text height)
Top Overlay:
  lines w0.254: 55.684,23.15 cw(c55.761,23.213) 55.69,23.142
  text "Brushless DC" at 32.818,49.467 h1.78
  text "Controller" at 32.811,47.993 h1.78
  text "REV.A" at 40.813,47.974 h0.84
  text "V" at 20.377,46.477 h1.78
  text "W" at 14.426,42.623 h1.78
  text "SDI" at 49.128,39.624 h1.3
  text "SCS" at 53.465,39.624 h1.3
  text "SDO" at 46.537,38.03 h1.3
  text "SCK" at 51.119,38.03 h1.3
  text "GND" at 55.42,38.03 h1.3
  text "U" at 11.094,37.145 h1.78
  text "VM" at 27.329,3.71 h1.78
  text "GND" at 30.414,3.694 h1.78
  text ".Layer_Name" at 14.656,-21.806 h1.52
Bottom Overlay:
  text ".Layer_Name" at 14.656,-21.806 h1.52
Top Paste:
  text ".Layer_Name" at 14.656,-21.806 h1.52
Bottom Paste:
  text ".Layer_Name" at 14.656,-21.806 h1.52
Top Solder:
  text ".Layer_Name" at 14.656,-21.806 h1.52
  text ".Layer_Name" at 14.656,-21.806 h1.52
Bottom Solder:
  text ".Layer_Name" at 14.656,-21.806 h1.52
Drill Guide:
  text ".Layer_Name" at 14.656,-21.806 h1.52
M1 Board Outline:
  circle w0.254: c30,30 r11
  circle w0.254: c30,30 r30
  text ".Layer_Name" at 14.656,-21.806 h1.52
M2 Board Dimensions:
  rectangle: -0.013,-7.252 3.162,-4.077
  rectangle: 3.162,-10.427 12.687,-7.252
  lines w0.178: -0.013,-7.252 25.387,-7.252 ; 3.162,-10.427 3.162,-4.077 ; 6.337,-10.427 6.337,-4.077 ; 12.687,-10.427 12.687,-4.077 ; 19.037,-10.427 19.037,-4.077 ; -0.013,-10.427 25.387,-10.427 25.387,-4.077 -0.013,-4.077 -0.013,-10.427
  lines w0.254: -0.013,-12.078 -0.013,-11.57 ; 1.511,-12.332 -0.013,-11.824 ; 1.511,-11.316 -0.013,-11.824 ; 6.187,-11.824 -0.013,-11.824 ; 19.188,-11.824 25.387,-11.824 ; 23.863,-12.332 25.387,-11.824 ; 23.863,-11.316 25.387,-11.824 ; 25.387,-12.078 25.387,-11.57
  text "25.4 (mm)" at 6.441,-12.738 h1.52
  text ".Layer_Name" at 14.656,-21.806 h1.52
M3 3D STEP Top:
  text ".Layer_Name" at 14.656,-21.806 h1.52
M4 3D STEP Bottom:
  text ".Layer_Name" at 14.656,-21.806 h1.52
M5 Assembly Top:
  circle w0.01: c30,30 r13.487
  circle w0.01: c36.744,41.68 r1.93
  circle w0.01: c36.744,18.32 r1.93
  circle w0.01: c16.513,30 r1.93
  circle w0.01: c30,30 r17
  lines w0.254: -7.417,-23.626 160.223,-23.626 ; -7.417,-18.462 160.274,-18.462 ; -7.417,-13.297 -7.417,-28.791 94.31,-28.791 160.274,-28.791 160.274,-13.297 -7.404,-13.297 -7.404,-28.791 32.614,-28.791 ; 55.194,-28.791 55.194,-13.297 ; 87.376,-18.462 87.376,-13.297 ; 108.712,-18.462 108.712,-13.297 ; 124.511,-28.956 124.511,-23.804 ; 14.431,36.816 cw(c30.032,29.993) 23.246,45.61 23.996,44.084 ccw(c29.827,30.217) 15.976,36.086 14.431,36.816
  text "COMPONENTS MARKED 'DNP' SHOULD NOT BE POPULATED." at 29.299,-8.09 h1.52
  text "ASSEMBLY VARIANT:" at 29.286,-11.024 h1.52
  text ".VariantName" at 55.601,-11.024 h1.52
  text "PCB VIEWED FROM TOP SIDE" at -5.804,-16.654 h1.52
  text "BOARD #:" at 57.099,-16.654 h1.52
  text ".PRJ_Number" at 70.955,-16.654 h1.52
  text "REV:" at 92.405,-16.654 h1.52
  text ".PCB_Rev" at 99.809,-16.654 h1.52
  text "SVN REV:" at 113.69,-16.654 h1.52
  text ".VersionControl_RevNumber" at 126.543,-16.654 h1.52
  text "IGNORE ->" at -5.804,-21.806 h1.52
  text "PLOT NAME =" at -5.804,-27.034 h1.52
  text ".plot_File_Name" at 14.656,-27.034 h1.52
  text "GENERATED    :" at 57.15,-27.034 h1.52
  text ".Print_Date" at 79.235,-27.034 h1.52
  text ".Print_Time" at 97.752,-27.034 h1.52
  text "TEXAS INSTRUMENTS" at 129.87,-27.034 h1.52
M6 Assembly Bottom:
  lines w0.254: -7.429,-18.474 160.261,-18.474 ; -7.379,-23.639 160.261,-23.639 ; 28.334,-28.969 28.334,-23.817 ; 44.133,-18.474 44.133,-13.31 ; 65.468,-18.474 65.468,-13.31 ; 97.65,-28.804 97.65,-13.31 ; 120.231,-28.804 160.249,-28.804 160.249,-13.31 -7.429,-13.31 -7.429,-28.804 58.534,-28.804 160.261,-28.804 160.261,-13.31
  text "COMPONENTS MARKED 'DNP' SHOULD NOT BE POPULATED." at 154.991,-8.077 h1.52
  text ".VariantName" at 128.473,-11.024 h1.52
  text "ASSEMBLY VARIANT:" at 154.864,-11.024 h1.52
  text ".VersionControl_RevNumber" at 26.302,-16.667 h1.52
  text "SVN REV:" at 39.154,-16.667 h1.52
  text ".PCB_Rev" at 53.035,-16.667 h1.52
  text "REV:" at 60.439,-16.667 h1.52
  text ".PRJ_Number" at 81.89,-16.667 h1.52
  text "BOARD #:" at 95.745,-16.667 h1.52
  text "PCB VIEWED FROM BOTTOM SIDE" at 158.648,-16.667 h1.52
  text "IGNORE ->" at 64.715,-21.806 h1.52
  text "TEXAS INSTRUMENTS" at 22.974,-27.047 h1.52
  text ".Print_Time" at 55.093,-27.047 h1.52
  text ".Print_Date" at 73.609,-27.047 h1.52
  text "GENERATED    :" at 95.694,-27.047 h1.52
  text ".plot_File_Name" at 138.189,-27.047 h1.52
  text "PLOT NAME =" at 158.648,-27.047 h1.52
M9 Title Sheet:
  drawing of 57 lines, arcs and shapes, not listed
  text "1" at 18.792,204.127 h1.78
  text "2" at 82.182,204.127 h1.78
  text "3" at 145.411,204.127 h1.78
  text "4" at 209.08,204.127 h1.78
  text "5" at 272.555,204.127 h1.78
  text "6" at 336.182,204.127 h1.78
  text "A" at -10.579,175.095 h1.78
  text "A" at 365.341,175.095 h1.78
  text "B" at -10.579,114.643 h1.78
  text "B" at 365.341,114.643 h1.78
  text "C" at -10.579,54.318 h1.78
  text "C" at 365.341,54.318 h1.78
  text "PROJECT TITLE:" at 288.125,7.048 h1.14
  text ".PRJ_Title" at 289.395,3.662 h1.78
  text "DESIGNED FOR:" at 288.125,-0.597 h1.14
  text ".PRJ_Customer" at 289.395,-4.153 h1.78
  text "D" at -10.579,-5.88 h1.78
  text "D" at 365.341,-5.88 h1.78
  text "FILE NAME:" at 288.125,-8.217 h1.14
  text ".PCB_File_Name_No_Path" at 289.395,-11.265 h1.78
  text "Texas Instruments (TI) and/or its licensors do not warrant the accuracy or completeness of this specification" at 161.9,-15.376 h1.14
  text "ENGINEER:" at 288.125,-15.583 h1.14
  text "LAYOUT BY:" at 326.352,-15.583 h1.14
  text "or any information contained therein. TI and/or its licensors do not warrant that this design will meet" at 160.757,-18.237 h1.14
  text ".PRJ_Engineer" at 289.395,-19.52 h1.78
  text ".PCB_Layout" at 327.635,-19.52 h1.78
  text "the specifications, will be suitable for your application or fit for any particular purpose, or will operate in" at 160.757,-21.099 h1.14
  text ".Layer_Name" at 14.656,-21.806 h1.52
  text "ALTIUM DESIGNER VERSION:" at 326.352,-23.457 h1.14
  text "an implementation. TI and/or its licensors do not warrant that the design is production worthy. You should" at 160.757,-23.961 h1.14
  text "completely validate and test your design implementation to confirm the system functionality for your application." at 161.9,-26.822 h1.14
  text ".print_Scale" at 289.395,-26.843 h1.78
  text ".Application_BuildNumber" at 327.635,-26.843 h1.78
  text "1" at 18.792,-32.093 h1.78
  text "2" at 82.182,-32.093 h1.78
  text "3" at 145.411,-32.093 h1.78
  text "4" at 209.08,-32.093 h1.78
  text "5" at 272.555,-32.093 h1.78
  text "6" at 336.182,-32.093 h1.78
M10 Fab Notes:
  drawing of 213 lines, arcs and shapes, not listed
  text "DESIGN INFORMATION" at 314.478,172.974 h1.52
  text "(REFER ALSO ARRAY/PANEL PROFILING INFORMATION)" at 305.294,168.866 h1.52
  text "BOARD SIZE" at 287.87,168.758 h1.52
  text "4724.4MIL" at 299.613,165.511 h1.52
  text "X" at 312.457,165.511 h1.52
  text "2952.8MIL" at 318.333,165.511 h1.52
  text "Number of Layers :" at 298.106,160.503 h1.52
  text "2" at 325.914,160.249 h1.52
  text "MIN. TRACK WIDTH:" at 298.106,156.972 h1.52
  text "10" at 325.374,156.972 h1.52
  text "MIL" at 329.881,156.972 h1.52
  text "MIN. CLEARANCE:" at 298.106,153.619 h1.52
  text "8" at 325.951,153.619 h1.52
  text "MIL" at 329.881,153.619 h1.52
  text "MIN. VIA PAD SIZE:" at 298.106,150.266 h1.52
  text "25" at 325.189,150.266 h1.52
  text "MIL" at 329.881,150.266 h1.52
  text "10" at 325.882,146.812 h1.52
  text "MIL" at 329.946,146.812 h1.52
  text "MIN. ANNULAR RING:" at 298.107,146.559 h1.52
  text "PER" at 294.824,143.561 h1.52
  text "IPC-D-275 CLASS 2 LEVEL C" at 300.412,143.561 h1.52
  text "MIL, HOLES" at 338.213,140.709 h1.52
  text "+/-" at 328.244,140.691 h1.52
  text "+/-" at 349.936,140.691 h1.52
  text "REGISTRATION TOLERANCES:" at 289.744,140.564 h1.52
  text "METAL" at 320.218,140.564 h1.52
  text "5" at 334.853,140.564 h1.52
  text "3" at 356.012,140.564 h1.52
  text "MIL" at 358.964,140.564 h1.52
  text "MATERIAL:" at 287.844,135.243 h1.52
  text "FR-4 High Tg" at 312.9,131.679 h1.52
  text "FR-408" at 298.538,131.461 h1.52
  text "X" at 309.003,131.461 h1.52
  text "OTHER" at 336.333,131.461 h1.52
  text "62 MIL (1.6mm) +/-10%" at 306.668,127.328 h1.52
  text "THICKNESS:" at 289.744,127.219 h1.52
  text "X" at 303.413,127.219 h1.52
  text "OTHER" at 339.305,127.219 h1.52
  text "TOLERANCE:" at 289.744,123.206 h1.52
  text "X" at 311.062,123.206 h1.52
  text "ANSI IPC-6012 TYPE 3 CLASS 2" at 315.81,123.206 h1.52
  text "OTHER +/-" at 315.81,119.244 h1.52
  text "BOW & TWIST:" at 289.744,115.256 h1.52
  text "X" at 311.062,115.256 h1.52
  text "ANSI IPC-6012 TYPE 3 CLASS 2" at 315.81,115.256 h1.52
  text "OTHER +/-" at 315.81,111.23 h1.52
  text "COPPER THICKNESS (FINISHED):" at 287.844,107.788 h1.52
  text "1.4MIL (1oz)" at 310.196,103.909 h1.52
  text "2MIL (1.4oz)" at 329.678,103.909 h1.52
  text "2.8MIL (2oz)" at 348.144,103.909 h1.52
  text "OUTER:" at 296.912,103.801 h1.52
  text "X" at 326.39,103.632 h1.52
  text "1.4MIL (1oz)" at 310.196,99.922 h1.52
  text "2.8MIL (2oz)" at 329.678,99.922 h1.52
  text "N/A" at 348.132,99.931 h1.52
  text "INNER SIGNAL:" at 289.57,99.813 h1.52
  text "X" at 344.932,99.822 h1.52
  text "DRILLING:" at 287.844,96.282 h1.52
  text "REFERENCE:" at 289.744,93.31 h1.52
  text "X" at 306.209,93.31 h1.52
  text "AS SHOWN" at 310.958,93.31 h1.52
  text "X" at 329.094,93.31 h1.52
  text "NC_DRILL FILES" at 332.574,93.31 h1.52
  text "PTH MIN COPPER THICKNESS:" at 289.744,89.297 h1.52
  text "X" at 324.039,89.297 h1.52
  text "1MIL" at 327.519,89.297 h1.52
  text "OTHER" at 340.143,89.297 h1.52
  text "BOARD FINISH:" at 287.844,85.259 h1.52
  text "SILKSCREEN:" at 291.787,82.261 h1.52
  text "X" at 315.886,82.261 h1.52
  text "TOP" at 319.086,82.261 h1.52
  text "BOTTOM" at 332.066,82.261 h1.52
  text "SILKSCREEN COLOR:" at 291.787,78.02 h1.52
  text "X" at 315.86,78.02 h1.52
  text "WHITE" at 319.086,78.02 h1.52
  text "OTHER" at 332.066,78.02 h1.52
  text "SOLDER RESIST COLOR:" at 291.787,73.702 h1.52
  text "X" at 306.208,69.658 h1.52
  text "GREEN" at 309.434,69.658 h1.52
  text "BLUE" at 324.446,69.658 h1.52
  text "OTHER" at 338.111,69.658 h1.52
  text "IMMERSION GOLD (ENIG)" at 314.794,64.87 h1.52
  text "ENEPIG" at 348.767,64.786 h1.52
  text "SURFACE FINISH:" at 287.844,64.761 h1.52
  text "X" at 310.045,64.761 h1.52
  text "IMM. TIN/SILVER OR EQUIV" at 296.215,60.773 h1.52
  text "OTHER" at 332.574,60.773 h1.52
  text "ARRAY/PANEL:" at 287.844,56.226 h1.52
  text "CUT AND TRIM PER MECH LAYER 1" at 314.794,56.118 h1.52
  text "N.C. ROUTE" at 314.794,52.264 h1.52
  text "X" at 332.04,52.264 h1.52
  text "V. SCORE" at 336.79,52.264 h1.52
  text "CERTIFICATION:" at 287.844,48.784 h1.52
  text "MATERIALS AND WORKMANSHIP FOR ALL PCBS" at 306.259,48.784 h1.52
  text "TO MEET OR EXCEED THE REQUIREMENTS OF:" at 306.259,46.295 h1.52
  text "X" at 296.773,42.828 h1.52
  text "ANSI IPC-A-600F CLASS ->" at 300.303,42.828 h1.52
  text "X" at 341.935,42.828 h1.52
  text "2" at 344.956,42.828 h1.52
  text "1" at 336.955,42.79 h1.52
  text "3" at 353.948,42.79 h1.52
  text "X" at 296.825,38.777 h1.52
  text "UL 94V-0" at 300.303,38.777 h1.52
  text "X" at 317.45,38.777 h1.52
  text "RoHS" at 320.928,38.777 h1.52
  text "OTHER" at 337.296,38.777 h1.52
  text "PER ORDER" at 347.381,38.777 h1.52
  text "ADDITIONAL REQUIREMENTS:" at 287.844,35.195 h1.52
  text "MICROSECTION:" at 289.744,32.274 h1.52
  text "YES" at 312.749,32.274 h1.52
  text "REQUIRED" at 334.631,28.308 h1.52
  text "BARE BOARD ELEC. TEST:" at 289.744,28.236 h1.52
  text "NONE" at 322.909,28.236 h1.52
  text "PER ORDER" at 349.668,28.236 h1.52
  text "X" at 346.202,28.194 h1.52
  text "MANUFACTURER'S UL:" at 289.744,24.248 h1.52
  text "RAIL" at 319.353,24.139 h1.52
  text "METAL" at 331.845,24.139 h1.52
  text "X" at 341.376,24.13 h1.52
  text "SILK" at 344.842,24.139 h1.52
  text ".Layer_Name" at 14.656,-21.806 h1.52
M11 Gerber Information:
  lines w0.254: -7.417,-23.626 160.223,-23.626 ; -7.417,-18.462 160.274,-18.462 ; -7.417,-13.297 -7.417,-28.791 94.31,-28.791 160.274,-28.791 160.274,-13.297 -7.404,-13.297 -7.404,-28.791 32.614,-28.791 ; 55.194,-28.791 55.194,-13.297 ; 87.376,-18.462 87.376,-13.297 ; 108.712,-18.462 108.712,-13.297 ; 124.511,-28.956 124.511,-23.804
  text "ALL ARTWORK VIEWED FROM TOP SIDE" at -5.804,-16.654 h1.52
  text "BOARD #:" at 57.099,-16.654 h1.52
  text ".PRJ_Number" at 70.955,-16.654 h1.52
  text "REV:" at 92.405,-16.654 h1.52
  text ".PCB_Rev" at 99.809,-16.654 h1.52
  text "SVN REV:" at 113.69,-16.654 h1.52
  text ".VersionControl_RevNumber" at 126.543,-16.654 h1.52
  text "LAYER NAME =" at -5.804,-21.806 h1.52
  text "PLOT NAME =" at -5.804,-27.034 h1.52
  text ".plot_File_Name" at 14.656,-27.034 h1.52
  text "GENERATED    :" at 57.15,-27.034 h1.52
  text ".Print_Date" at 79.235,-27.034 h1.52
  text ".Print_Time" at 97.752,-27.034 h1.52
  text "TEXAS INSTRUMENTS" at 129.87,-27.034 h1.52
M12 Stackup:
  lines w0.152: 288.544,189.484 353.314,189.484 ; 288.544,192.136 353.314,192.136 ; 287.02,177.165 ccw(c287.884,177.165) 287.884,176.301 353.974,176.301 ccw(c353.974,177.165) 354.838,177.165 354.838,195.097 ccw(c353.974,195.097) 353.974,195.961 287.884,195.961 ccw(c287.884,195.097) 287.02,195.097 287.02,177.165
  text "The Stackup Legend below this is static." at 294.78,200.012 h1.52
  text "If you change the stackup, update the Legend." at 295.034,197.726 h1.52
  text "Layer Stack Up Detail for: Ref_Design.PcbDoc" at 288.544,192.966 h1.45
  text "Layer" at 288.544,191.145 h0.61
  text "Gerber" at 311.298,191.145 h0.61
  text "Copper" at 325.611,191.145 h0.61
  text "Dielectric" at 340.92,191.145 h0.61
  text "Name" at 288.544,189.926 h0.61
  text "Document" at 311.298,189.926 h0.61
  text "Thickness" at 325.611,189.926 h0.61
  text "Material" at 340.92,189.926 h0.61
  text "Top Solder Mask" at 288.544,187.565 h0.86
  text "(.GTS)" at 311.298,187.565 h0.86
  text "Solder Resist" at 340.92,187.565 h0.86
  text "Top Layer" at 288.544,185.107 h0.86
  text "(.GTL)" at 311.298,185.107 h0.86
  text "1.4mil" at 325.611,185.107 h0.86
  text "FR-4" at 340.92,183.879 h0.86
  text "Bottom Layer" at 288.544,182.65 h0.86
  text "(.GBL)" at 311.298,182.65 h0.86
  text "1.4mil" at 325.611,182.65 h0.86
  text "Bottom Solder Mask" at 288.544,180.192 h0.86
  text "(.GBS)" at 311.298,180.192 h0.86
  text "Solder Resist" at 340.92,180.192 h0.86
  text ".Layer_Name" at 14.656,-21.806 h1.52
M13 Component Bodies Top:
  text ".Layer_Name" at 14.656,-21.806 h1.52
M14 Component Bodies Bottom:
  text ".Layer_Name" at 14.656,-21.806 h1.52
M15 Courtyards Top:
  text ".Layer_Name" at 14.656,-21.806 h1.52
M16 Courtyards Bottom:
  text ".Layer_Name" at 14.656,-21.806 h1.52
Drill Drawing:
  text ".legend" at 65.105,30.667 h1.52
  text "Drill Table" at 65.105,27.48 h1.52
  text ".Layer_Name" at 14.656,-21.806 h1.52

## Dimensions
0,0 to 60,30 on M2 Board Dimensions
0,0 to 0,30 on M2 Board Dimensions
